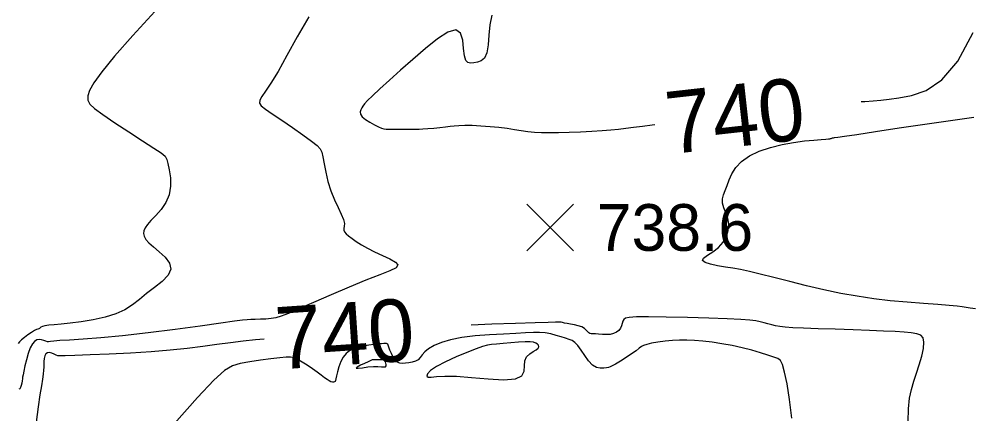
# Model space of a CAD drawing. Extents: x 2566142 to 2571431, y 418755 to 421584.
# Drawn here: x 2569336.4 to 2569642.8, y 420498.8 to 420625.6 of the extents above; entities that cross this region are included whole.
import ezdxf

# ---------------------------------------------------------------- set-up
doc = ezdxf.new("R2010")
doc.units = 0
for name, color, linetype in [('Contour_ADS_Label_Major', 7, 'Continuous'), ('Contour_ADS_Major', 7, 'Continuous'), ('Contour_ADS_Minor', 7, 'Continuous'), ('Contour_ADS_Spot_Elevation', 7, 'Continuous')]:
    doc.layers.add(name, color=color, linetype=linetype)

# ---------------------------------------------------------------- blocks, each defined once
blk = doc.blocks.new('S750')
at = {"layer": 'Contour_ADS_Spot_Elevation'}
for p, q in [((-0.5, 0.498), (0.5, -0.498)), ((-0.498, -0.5), (0.498, 0.5))]:
    blk.add_line(p, q, dxfattribs=at)

msp = doc.modelspace()

# ---------------------------------------------------------------- linework, layer by layer
at = {"layer": 'Contour_ADS_Major'}
for points in [[(2569488.26, 420626.77), (2569487.65, 420623.68), (2569487.34, 420620.37), (2569487.09, 420617.24), (2569486.68, 420614.7), (2569485.9, 420613.05), (2569484.86, 420612.15), (2569483.67, 420611.73), (2569482.49, 420611.56), (2569481.43, 420611.46), (2569480.55, 420611.61), (2569479.87, 420612.29), (2569479.44, 420613.77), (2569479.22, 420616.14), (2569478.93, 420618.82), (2569478.2, 420621.06), (2569476.68, 420622.09), (2569474.14, 420621.37), (2569470.78, 420619.21), (2569466.93, 420616.12), (2569462.89, 420612.62), (2569458.97, 420609.16), (2569455.38, 420605.96), (2569452.3, 420603.18), (2569449.91, 420600.96), (2569448.33, 420599.39), (2569447.39, 420598.34), (2569446.87, 420597.63), (2569446.53, 420597.05), (2569446.21, 420596.44), (2569446.01, 420595.77), (2569446.09, 420595.03), (2569446.62, 420594.21), (2569447.69, 420593.32), (2569449.11, 420592.42), (2569450.61, 420591.61), (2569451.92, 420590.97), (2569452.85, 420590.56), (2569453.56, 420590.34), (2569454.31, 420590.25), (2569455.32, 420590.23), (2569456.77, 420590.23), (2569458.49, 420590.24), (2569460.24, 420590.24), (2569461.79, 420590.23), (2569462.97, 420590.22), (2569463.93, 420590.21), (2569464.9, 420590.22), (2569466.12, 420590.28), (2569467.74, 420590.39), (2569469.62, 420590.55), (2569471.56, 420590.74), (2569473.35, 420590.94), (2569474.84, 420591.14), (2569476.22, 420591.32), (2569477.71, 420591.44), (2569479.58, 420591.49), (2569481.98, 420591.46), (2569484.77, 420591.33), (2569487.7, 420591.12), (2569490.55, 420590.84)], [(2569606.88, 420599.1), (2569608.09, 420599.15), (2569610.77, 420599.33), (2569613.22, 420599.58), (2569615.85, 420599.9), (2569619.04, 420600.32), (2569623.08, 420600.98), (2569627.78, 420602.6), (2569632.84, 420606.01), (2569637.95, 420612.08), (2569642.84, 420621.25)], [(2569490.55, 420590.84), (2569493.15, 420590.5), (2569495.51, 420590.14), (2569497.71, 420589.79), (2569499.84, 420589.5), (2569501.98, 420589.29), (2569504.25, 420589.17), (2569506.78, 420589.13), (2569509.72, 420589.16), (2569513.12, 420589.26), (2569516.77, 420589.41), (2569520.39, 420589.6), (2569523.68, 420589.81), (2569526.46, 420590.03), (2569528.9, 420590.27), (2569531.26, 420590.54), (2569533.81, 420590.86), (2569536.71, 420591.23), (2569539.8, 420591.61), (2569540.62, 420591.7)], [(2569557.93, 420529.57), (2569551.07, 420529.74), (2569544.3, 420529.87), (2569538.59, 420529.94), (2569534.7, 420529.94), (2569532.4, 420529.82), (2569531.21, 420529.57), (2569530.67, 420529.16), (2569530.38, 420528.57), (2569530.16, 420527.85), (2569529.92, 420527.07), (2569529.57, 420526.31), (2569529.01, 420525.63), (2569528.26, 420525.06), (2569527.33, 420524.63), (2569526.24, 420524.36), (2569525.02, 420524.27), (2569523.77, 420524.31), (2569522.58, 420524.41), (2569521.56, 420524.5), (2569520.78, 420524.53), (2569520.2, 420524.56), (2569519.76, 420524.65), (2569519.39, 420524.86), (2569519.02, 420525.24), (2569518.58, 420525.73), (2569517.98, 420526.25), (2569517.15, 420526.74), (2569516.04, 420527.12), (2569514.78, 420527.42), (2569513.52, 420527.65), (2569512.42, 420527.83), (2569511.58, 420527.99), (2569510.99, 420528.13), (2569510.54, 420528.23), (2569510.18, 420528.3), (2569509.74, 420528.32), (2569508.67, 420528.3), (2569506.37, 420528.21), (2569502.2, 420528.07), (2569495.85, 420527.85), (2569488.25, 420527.58), (2569481.67, 420527.33)], [(2569622.03, 420496.41), (2569622.06, 420500.46), (2569622.4, 420503.85), (2569623.02, 420506.71), (2569623.81, 420509.3), (2569624.69, 420511.88), (2569625.57, 420514.61), (2569626.34, 420517.34), (2569626.87, 420519.84), (2569627.05, 420521.87), (2569626.77, 420523.24), (2569626.01, 420524.08), (2569624.75, 420524.55), (2569622.99, 420524.82), (2569620.69, 420525.04), (2569617.77, 420525.24), (2569614.11, 420525.43), (2569609.62, 420525.62), (2569604.28, 420525.8), (2569598.58, 420525.99), (2569593.09, 420526.17), (2569588.4, 420526.34), (2569584.93, 420526.5), (2569582.49, 420526.67), (2569580.77, 420526.86), (2569579.43, 420527.1), (2569578.19, 420527.4), (2569576.96, 420527.74), (2569575.73, 420528.08), (2569574.46, 420528.41), (2569573.05, 420528.7), (2569571.12, 420528.95), (2569568.22, 420529.17), (2569563.9, 420529.38), (2569557.93, 420529.57)], [(2569415.16, 420522.78), (2569412.35, 420522.56), (2569408.38, 420522.14), (2569404.28, 420521.65), (2569399.98, 420521.08), (2569395.41, 420520.47), (2569390.45, 420519.84), (2569384.98, 420519.25), (2569378.88, 420518.72), (2569372.17, 420518.3), (2569365.39, 420517.98), (2569359.23, 420517.74), (2569354.37, 420517.57), (2569351.28, 420517.45), (2569349.62, 420517.42), (2569348.83, 420517.48), (2569348.36, 420517.67), (2569347.75, 420517.98), (2569347, 420518.3), (2569346.24, 420518.5), (2569345.56, 420518.46), (2569345.06, 420518.08), (2569344.72, 420517.42), (2569344.52, 420516.59), (2569344.41, 420515.69), (2569344.36, 420514.8), (2569344.33, 420513.87), (2569344.27, 420512.82), (2569344.15, 420511.55), (2569343.92, 420509.96), (2569343.59, 420507.85), (2569343.14, 420504.99), (2569342.59, 420501.14), (2569341.94, 420496.22)]]:
    msp.add_lwpolyline(points, dxfattribs=at)
at = {"layer": 'Contour_ADS_Minor'}
for points in [[(2569380.04, 420627.99), (2569372.98, 420620.3), (2569367.11, 420613.66), (2569362.99, 420608.66), (2569360.44, 420605.1), (2569359.07, 420602.63), (2569358.52, 420600.9), (2569358.5, 420599.55), (2569359.14, 420598.28), (2569360.68, 420596.82)], [(2569429.53, 420626.26), (2569425.76, 420619.88), (2569422.45, 420613.87), (2569419.63, 420608.78), (2569417.34, 420605.02), (2569415.59, 420602.41), (2569414.38, 420600.66), (2569413.73, 420599.48), (2569413.65, 420598.58), (2569414.23, 420597.71), (2569415.57, 420596.65), (2569417.75, 420595.16), (2569420.78, 420593.11), (2569424.23, 420590.75), (2569427.6, 420588.4), (2569430.38, 420586.42), (2569432.17, 420585.01), (2569433.17, 420583.93), (2569433.66, 420582.81), (2569433.98, 420581.29), (2569434.37, 420579.09), (2569434.91, 420576.37), (2569435.63, 420573.39), (2569436.56, 420570.38), (2569437.69, 420567.58), (2569438.87, 420565.08), (2569439.92, 420562.94), (2569440.64, 420561.22), (2569440.92, 420559.95), (2569440.88, 420559.04), (2569440.74, 420558.36), (2569440.71, 420557.8), (2569440.93, 420557.25), (2569441.46, 420556.66), (2569442.27, 420555.98), (2569443.36, 420555.17), (2569444.73, 420554.21), (2569446.38, 420553.14), (2569448.33, 420552), (2569450.6, 420550.84), (2569453.13, 420549.7), (2569455.53, 420548.61), (2569457.35, 420547.58), (2569458.13, 420546.63), (2569457.52, 420545.73), (2569455.52, 420544.74), (2569452.25, 420543.48), (2569447.82, 420541.79), (2569442.43, 420539.56), (2569436.62, 420537.05), (2569431.04, 420534.58), (2569426.32, 420532.5), (2569422.91, 420531.06), (2569420.57, 420530.17), (2569418.86, 420529.68), (2569417.35, 420529.43), (2569415.69, 420529.29), (2569413.96, 420529.2), (2569412.3, 420529.16), (2569410.87, 420529.12), (2569409.68, 420529.06), (2569408.15, 420528.91), (2569405.57, 420528.57), (2569401.2, 420527.96)], [(2569360.68, 420596.82), (2569363.33, 420594.88), (2569367.18, 420592.28), (2569371.67, 420589.35), (2569376.08, 420586.49), (2569379.72, 420584.14), (2569382.05, 420582.58), (2569383.3, 420581.51), (2569383.9, 420580.52), (2569384.25, 420579.17), (2569384.66, 420577.16), (2569385.02, 420574.65), (2569385.09, 420571.88), (2569384.65, 420569.14), (2569383.55, 420566.65), (2569382.02, 420564.45), (2569380.33, 420562.55), (2569378.79, 420560.94), (2569377.64, 420559.63), (2569376.89, 420558.54), (2569376.49, 420557.59), (2569376.41, 420556.72), (2569376.63, 420555.83), (2569377.18, 420554.86), (2569378.13, 420553.76), (2569379.55, 420552.45), (2569381.42, 420550.9), (2569383.31, 420549.15), (2569384.74, 420547.26), (2569385.18, 420545.3), (2569384.31, 420543.31), (2569382.42, 420541.32), (2569379.96, 420539.36), (2569377.4, 420537.44), (2569375.08, 420535.58), (2569372.84, 420533.84), (2569370.42, 420532.26), (2569367.54, 420530.92), (2569364.05, 420529.84), (2569360.19, 420529), (2569356.32, 420528.39), (2569352.8, 420527.95), (2569349.91, 420527.66), (2569347.66, 420527.46), (2569345.96, 420527.31), (2569344.74, 420527.13), (2569343.93, 420526.89), (2569343.44, 420526.63), (2569343.14, 420526.39), (2569342.96, 420526.21), (2569342.77, 420526.12), (2569342.5, 420526.05), (2569342.07, 420525.89), (2569341.39, 420525.55), (2569340.41, 420524.98), (2569339.28, 420524.23), (2569338.15, 420523.4), (2569337.21, 420522.62), (2569336.56, 420521.96), (2569336.17, 420521.45)], [(2569597.09, 420587.22), (2569597.29, 420587.28), (2569597.5, 420587.36), (2569597.74, 420587.43), (2569597.99, 420587.49), (2569598.37, 420587.54), (2569599.36, 420587.67), (2569601.53, 420587.98), (2569605.46, 420588.55), (2569611.5, 420589.46), (2569619.08, 420590.61), (2569627.38, 420591.85), (2569635.61, 420593.04), (2569643.13, 420594.07)], [(2569643.58, 420532.51), (2569641.89, 420532.79), (2569640.62, 420533.01), (2569639.37, 420533.21), (2569637.7, 420533.41), (2569635.18, 420533.63), (2569631.5, 420533.9), (2569626.87, 420534.23), (2569621.68, 420534.65), (2569616.26, 420535.17), (2569610.92, 420535.81), (2569605.63, 420536.58), (2569600.32, 420537.52), (2569594.91, 420538.64), (2569589.37, 420539.93), (2569583.93, 420541.3), (2569578.88, 420542.6), (2569574.5, 420543.72), (2569570.98, 420544.54), (2569568.13, 420545.13), (2569565.65, 420545.58), (2569563.27, 420545.97), (2569560.8, 420546.39), (2569558.5, 420546.86), (2569556.76, 420547.41), (2569555.94, 420548.06), (2569556.3, 420548.82), (2569557.54, 420549.74), (2569559.26, 420550.87), (2569561.03, 420552.25), (2569562.52, 420553.92), (2569563.59, 420555.79), (2569564.23, 420557.75), (2569564.38, 420559.72), (2569564.04, 420561.59), (2569563.42, 420563.35), (2569562.77, 420564.98), (2569562.33, 420566.47), (2569562.31, 420567.83), (2569562.64, 420569.15), (2569563.18, 420570.54), (2569563.83, 420572.11), (2569564.5, 420573.94), (2569565.35, 420575.93), (2569566.6, 420577.96), (2569568.43, 420579.89), (2569571.01, 420581.62), (2569574.17, 420583.11), (2569577.73, 420584.34), (2569581.47, 420585.31), (2569585.18, 420585.99), (2569588.65, 420586.45), (2569591.67, 420586.74), (2569594.01, 420586.91), (2569595.55, 420587.02), (2569596.43, 420587.1), (2569596.86, 420587.16), (2569597.09, 420587.22)], [(2569401.2, 420527.96), (2569394.62, 420527.04), (2569386.52, 420525.94), (2569377.87, 420524.83), (2569369.64, 420523.87), (2569362.64, 420523.21), (2569357, 420522.79), (2569352.65, 420522.53), (2569349.55, 420522.35), (2569347.61, 420522.17), (2569346.51, 420522.03), (2569345.93, 420521.97), (2569345.52, 420522.01), (2569345, 420522.2), (2569344.36, 420522.44), (2569343.64, 420522.64), (2569342.89, 420522.72), (2569342.15, 420522.56), (2569341.42, 420522.11), (2569340.72, 420521.27), (2569340.04, 420519.99), (2569339.39, 420518.23), (2569338.8, 420516.23), (2569338.3, 420514.25), (2569337.93, 420512.58), (2569337.7, 420511.41), (2569337.57, 420510.63), (2569337.5, 420510.04), (2569337.42, 420509.45), (2569337.3, 420508.72), (2569337.13, 420507.93), (2569336.9, 420507.26), (2569336.64, 420506.83), (2569336.35, 420506.76)], [(2569534.67, 420519.12), (2569533.18, 420518.08), (2569531.38, 420516.89), (2569529.55, 420515.75), (2569528.01, 420514.82), (2569526.95, 420514.23), (2569526.25, 420513.92), (2569525.69, 420513.77), (2569525.06, 420513.65), (2569524.19, 420513.5), (2569523.11, 420513.46), (2569521.89, 420513.73), (2569520.6, 420514.48), (2569519.33, 420515.82), (2569518.1, 420517.53), (2569516.95, 420519.29), (2569515.91, 420520.78), (2569514.97, 420521.77), (2569514.08, 420522.37), (2569513.11, 420522.75), (2569511.96, 420523.09), (2569510.56, 420523.53), (2569508.96, 420524.03), (2569507.23, 420524.49), (2569505.44, 420524.82), (2569503.63, 420524.97), (2569501.6, 420524.95), (2569499.13, 420524.83), (2569495.98, 420524.65), (2569492.01, 420524.47), (2569487.54, 420524.23), (2569482.96, 420523.87), (2569478.68, 420523.36), (2569475.03, 420522.64), (2569472.05, 420521.76), (2569469.71, 420520.77), (2569467.97, 420519.74), (2569466.77, 420518.72), (2569465.94, 420517.76), (2569465.28, 420516.91), (2569464.59, 420516.22), (2569463.72, 420515.72), (2569462.71, 420515.39), (2569461.63, 420515.18), (2569460.57, 420515.07), (2569459.59, 420515.03), (2569458.7, 420515.12), (2569457.9, 420515.44), (2569457.19, 420516.06), (2569456.55, 420517.02), (2569456.01, 420518.17), (2569455.56, 420519.33), (2569455.23, 420520.29), (2569455, 420520.91), (2569454.83, 420521.24), (2569454.66, 420521.37), (2569454.43, 420521.41), (2569454.07, 420521.42), (2569453.54, 420521.41), (2569452.78, 420521.37), (2569451.72, 420521.27), (2569450.35, 420521.11), (2569448.76, 420520.87), (2569447.08, 420520.57), (2569445.43, 420520.19), (2569443.93, 420519.71), (2569442.6, 420519.09), (2569441.45, 420518.24), (2569440.5, 420517.09), (2569439.73, 420515.61), (2569439.15, 420513.97), (2569438.71, 420512.37), (2569438.4, 420511.04), (2569438.2, 420510.12), (2569438.06, 420509.58), (2569437.92, 420509.28), (2569437.73, 420509.14), (2569437.46, 420509.05), (2569437.08, 420509.04), (2569436.61, 420509.14), (2569436.04, 420509.39), (2569435.36, 420509.83), (2569434.53, 420510.44), (2569433.5, 420511.24), (2569432.22, 420512.2), (2569430.68, 420513.3), (2569429.01, 420514.44), (2569427.37, 420515.48), (2569425.92, 420516.31), (2569424.74, 420516.83), (2569423.6, 420517.05), (2569422.18, 420517.04), (2569420.14, 420516.84), (2569417.29, 420516.51), (2569413.93, 420516.07), (2569410.51, 420515.55), (2569407.45, 420515), (2569404.98, 420514.3), (2569402.44, 420512.79), (2569398.99, 420509.65), (2569393.78, 420504.08)], [(2569584.67, 420497.48), (2569583.91, 420503.41), (2569583.09, 420508.44), (2569582.32, 420512.24), (2569581.68, 420514.64), (2569581.01, 420515.95), (2569580.12, 420516.62), (2569578.81, 420517.08), (2569576.92, 420517.7), (2569574.52, 420518.46), (2569571.73, 420519.28), (2569568.66, 420520.08), (2569565.43, 420520.78), (2569562.16, 420521.36), (2569558.99, 420521.83), (2569556.02, 420522.17), (2569553.35, 420522.4), (2569550.91, 420522.51), (2569548.59, 420522.5), (2569546.27, 420522.38), (2569543.9, 420522.15), (2569541.61, 420521.84), (2569539.59, 420521.5), (2569538.02, 420521.15), (2569537.01, 420520.82), (2569536.32, 420520.42), (2569535.64, 420519.89), (2569534.67, 420519.12)], [(2569393.78, 420504.08), (2569386.29, 420495.6)]]:
    msp.add_lwpolyline(points, dxfattribs=at)
for points in [[(2569476.88, 420510.93), (2569481.73, 420510.56), (2569487.07, 420510.07), (2569492.05, 420509.8), (2569495.86, 420510.05), (2569497.92, 420511.04), (2569498.65, 420512.56), (2569498.73, 420514.29), (2569498.82, 420515.91), (2569499.42, 420517.17), (2569500.43, 420518.11), (2569501.56, 420518.82), (2569502.53, 420519.39), (2569503.11, 420519.92), (2569503.32, 420520.4), (2569503.24, 420520.85), (2569502.93, 420521.24), (2569502.45, 420521.57), (2569501.7, 420521.82), (2569500.58, 420521.97), (2569498.95, 420522), (2569496.79, 420521.89), (2569494.32, 420521.69), (2569491.87, 420521.45), (2569489.75, 420521.24), (2569488.17, 420521.08), (2569486.83, 420520.87), (2569485.31, 420520.46), (2569483.2, 420519.73), (2569480.25, 420518.58), (2569476.8, 420517.15), (2569473.39, 420515.59), (2569470.52, 420514.08), (2569468.59, 420512.76), (2569467.59, 420511.71), (2569467.38, 420510.97), (2569467.81, 420510.59), (2569468.81, 420510.58), (2569470.53, 420510.78), (2569473.15, 420510.96), (2569476.88, 420510.93)], [(2569444.74, 420513.5), (2569445.39, 420513.46), (2569446.75, 420513.64), (2569448.48, 420513.89), (2569450.22, 420514.06), (2569451.67, 420514.07), (2569452.79, 420513.98), (2569453.6, 420513.91), (2569454.1, 420513.97), (2569454.33, 420514.26), (2569454.34, 420514.69), (2569454.24, 420515.16), (2569454.09, 420515.58), (2569453.95, 420515.87), (2569453.79, 420516.03), (2569453.54, 420516.11), (2569453.14, 420516.14), (2569452.57, 420516.17), (2569451.89, 420516.19), (2569451.21, 420516.2), (2569450.64, 420516.21), (2569450.23, 420516.2), (2569449.87, 420516.13), (2569449.36, 420515.95), (2569448.55, 420515.59), (2569447.35, 420515.05), (2569446.06, 420514.42), (2569445.06, 420513.85), (2569444.74, 420513.5)]]:
    msp.add_lwpolyline(points, close=True, dxfattribs=at)

# ---------------------------------------------------------------- block references
at = {"layer": 'Contour_ADS_Spot_Elevation', "xscale": 15, "yscale": 15}
msp.add_blockref('S750', (2569506.99, 420558.67), dxfattribs=at)

# ---------------------------------------------------------------- texts
at = {"layer": 'Contour_ADS_Label_Major'}
for rotation, p in [(6.3712, (2569545.31, 420582.16)), (3.9126, (2569419.44, 420513.05))]:
    msp.add_text('740', height=20, rotation=rotation, dxfattribs=at).set_placement(p)
at = {"layer": 'Contour_ADS_Spot_Elevation'}
msp.add_text('738.6', height=15, dxfattribs=at).set_placement((2569521.99, 420551.17))

doc.saveas('drawing.dxf')
